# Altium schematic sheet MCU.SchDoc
size A4; SheetNumber: 2; SheetTotal: 2
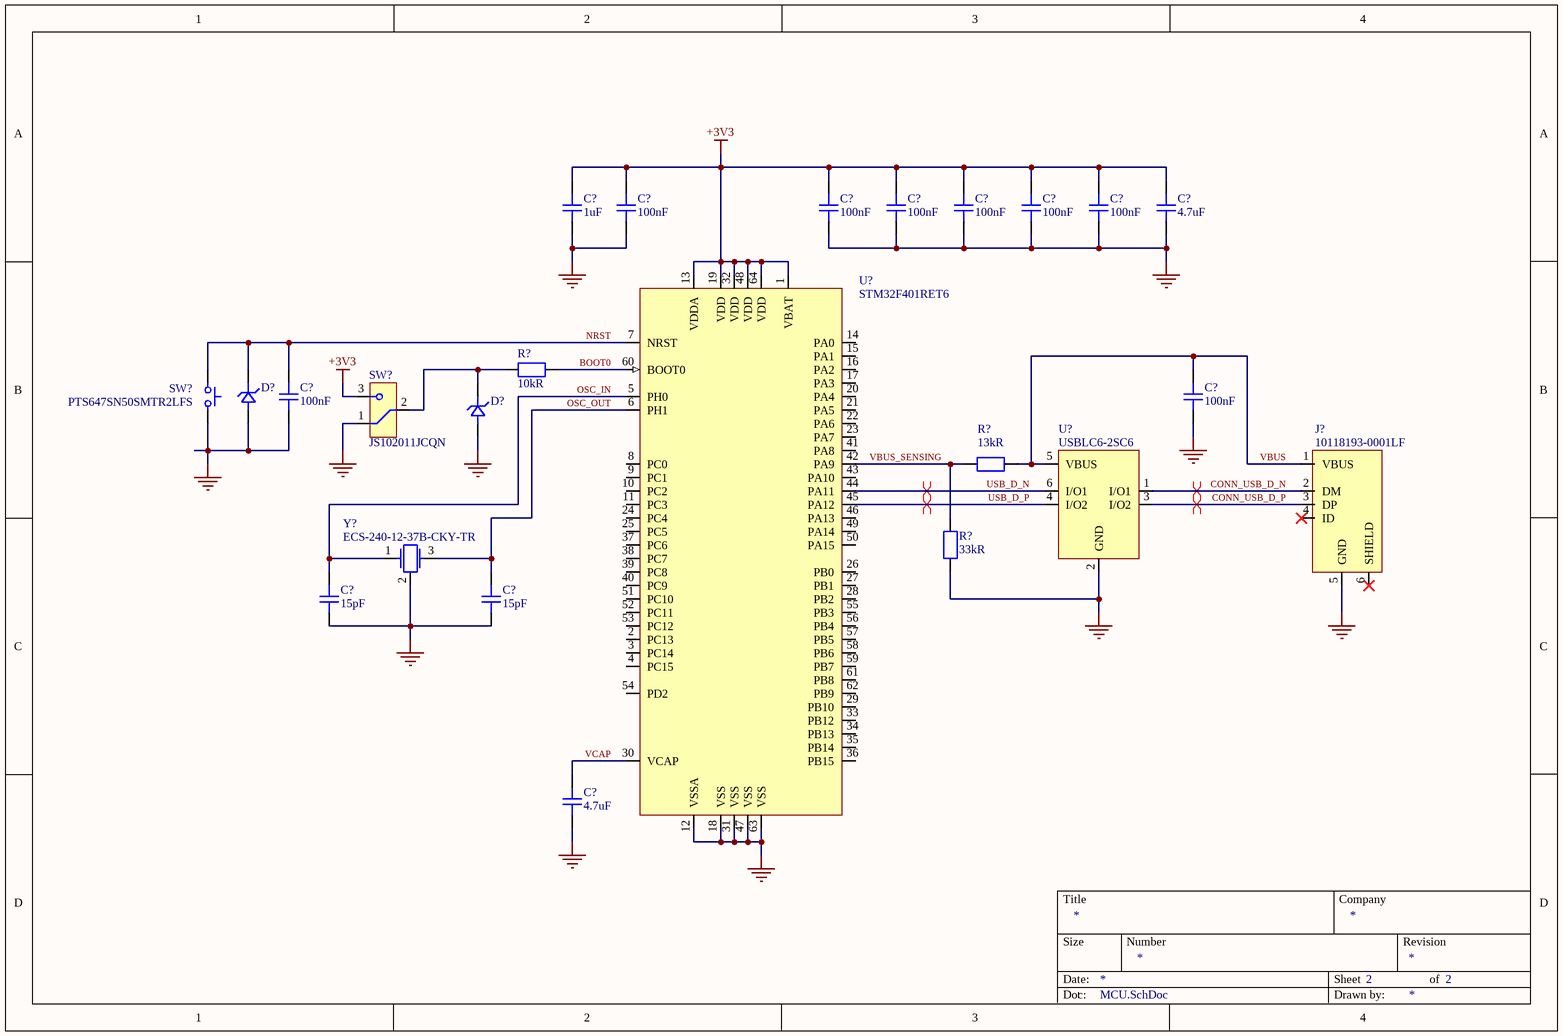
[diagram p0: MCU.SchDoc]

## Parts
(Parts that share a designator on the sheet are numbered #1, #2 ... from top to bottom, then left to right.)
C?#1  value 1uF  [C_Yageo_CC_0402_A]  (hidden comment: CC0402MRX5R6BB105)
C?#2  value 100nF  [C_Yageo_CC_0402_A]  (hidden comment: CC0402MRX5R6BB104)
C?#3  value 100nF  [C_Yageo_CC_0402_A]  (hidden comment: CC0402MRX5R6BB104)
C?#4  value 100nF  [C_Yageo_CC_0402_A]  (hidden comment: CC0402MRX5R6BB104)
C?#5  value 100nF  [C_Yageo_CC_0402_A]  (hidden comment: CC0402MRX5R6BB104)
C?#6  value 100nF  [C_Yageo_CC_0402_A]  (hidden comment: CC0402MRX5R6BB104)
C?#7  value 100nF  [C_Yageo_CC_0402_A]  (hidden comment: CC0402MRX5R6BB104)
C?#8  value 4.7uF  [C_Yageo_CC_0402_A]  (hidden comment: CC0402MRX5R6BB475)
C?#9  value 100nF  [C_Yageo_CC_0402_A]  (hidden comment: CC0402MRX5R6BB104)
C?#10  value 100nF  [C_Yageo_CC_0402_A]  (hidden comment: CC0402MRX5R6BB104)
C?#11  value 15pF  [C_Yageo_CC_0402_A]  (hidden comment: CC0402JRNPO9BN150)
C?#12  value 15pF  [C_Yageo_CC_0402_A]  (hidden comment: CC0402JRNPO9BN150)
C?#13  value 4.7uF  [C_Yageo_CC_0402_A]  (hidden comment: CC0402MRX5R6BB475)
D?#1  CPDU3V3UP  [D_TVS_Uni_CompChipTech_CPDU3V3UP_A]  (value not drawn)
D?#2  CPDU3V3UP  [D_TVS_Uni_CompChipTech_CPDU3V3UP_A]  (value not drawn)
J?  10118193-0001LF  [J_USB_Micro-B_Amphenol_10118193-0001LF]
R?#1  value 10kR  [R_Yageo_RCL_0402_A]  (hidden comment: RC0402FR-0710KL)
R?#2  value 13kR  [R_Yageo_RCL_0402_A]  (hidden comment: RC0402FR-0713KL)
R?#3  value 33kR  [R_Yageo_RCL_0402_A]  (hidden comment: RC0402FR-0733KL)
SW?#1  PTS647SN50SMTR2LFS  [SW_Tactitle_SPST_C&K_PTS647SN50SMTR2LFS]
SW?#2  JS102011JCQN  [SW_Slide_C&K_JS102011JCQN]
U?#1  USBLC6-2SC6  [U_STM32_SOT-23-6L_USBLC6-2-B]
U?#2  STM32F401RET6  [U_STM32F401xD/xE_B]
Y?  ECS-240-12-37B-CKY-TR  [Y_Crystal_GND24_ECS_240-12-37B-CKY-TR]

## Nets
+3V3: C?#1.2 C?#2.2 C?#3.2 C?#4.2 C?#5.2 C?#6.2 C?#7.2 C?#8.2 SW?#2.3 U?#2.1(VBAT) U?#2.13(VDDA) U?#2.19(VDD) U?#2.32(VDD) U?#2.48(VDD) U?#2.64(VDD)
GND: C?#1.1 C?#2.1 C?#3.1 C?#4.1 C?#5.1 C?#6.1 C?#7.1 C?#8.1 C?#9.1 C?#10.1 C?#11.1 C?#12.1 C?#13.1 D?#1.2 D?#2.2 J?.5(GND) R?#3.1 SW?#1.2 SW?#2.1 U?#1.2(GND) U?#2.12(VSSA) U?#2.18(VSS) U?#2.31(VSS) U?#2.47(VSS) U?#2.63(VSS) Y?.2
BOOT0: R?#1.2 U?#2.60(BOOT0)
CONN_USB_D_N: J?.2(DM) U?#1.1(I/O1)
CONN_USB_D_P: J?.3(DP) U?#1.3(I/O2)
NRST: C?#9.2 D?#1.1 SW?#1.1 U?#2.7(NRST)
OSC_IN: C?#11.2 U?#2.5(PH0) Y?.1
OSC_OUT: C?#12.2 U?#2.6(PH1) Y?.3
USB_D_N: U?#1.6(I/O1) U?#2.44(PA11)
USB_D_P: U?#1.4(I/O2) U?#2.45(PA12)
VBUS: C?#10.2 J?.1(VBUS) R?#2.2 U?#1.5(VBUS)
VBUS_SENSING: R?#2.1 R?#3.2 U?#2.42(PA9)
VCAP: C?#13.2 U?#2.30(VCAP)
NetD?#2_1: D?#2.1 R?#1.1 SW?#2.2

Not connected (* = marked no-connect by the designer): J? 4(ID)* 6(SHIELD)*; U?#2 2(PC13) 3(PC14) 4(PC15) 8(PC0) 9(PC1) 10(PC2) 11(PC3) 14(PA0) 15(PA1) 16(PA2) 17(PA3) 20(PA4) 21(PA5) 22(PA6) 23(PA7) 24(PC4) 25(PC5) 26(PB0) 27(PB1) 28(PB2) 29(PB10) 33(PB12) 34(PB13) 35(PB14) 36(PB15) 37(PC6) 38(PC7) 39(PC8) 40(PC9) 41(PA8) 43(PA10) 46(PA13) 49(PA14) 50(PA15) 51(PC10) 52(PC11) 53(PC12) 54(PD2) 55(PB3) 56(PB4) 57(PB5) 58(PB6) 59(PB7) 61(PB8) 62(PB9)

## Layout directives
differential pair; differential pair class USB: CONN_USB_D_N, CONN_USB_D_P
differential pair: USB_D_N, USB_D_P

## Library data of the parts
C?#1 = CMP-001-00016-7: Multilayer Ceramic Capacitor, 1 uF, 50 V, ± 10%, X5R, 0402 [1005 Metric]; Voltage Rating (DC): 10V; Tolerance: 20%; Temperature Coefficient: 30ppm/°C
C?#2-C?#7 C?#9 = CMP-001-00009-8: Multilayer Ceramic Capacitor, 0.1 uF, 25 V, ± 20%, X7R, 0402 [1005 Metric]; Dielectric: X5R; Temperature Coefficient: 30ppm/°C; Voltage Rating: 10V
C?#8 C?#13 = CMP-001-00015-8: Multilayer Ceramic Capacitor, 4.7 uF, 50 V, ± 10%, X5R, 0402 [1005 Metric]; Tolerance: 20%; Temperature Coefficient: 30ppm/°C; Voltage Rating (DC): 10V
C?#10 = CMP-001-00009-8: Multilayer Ceramic Capacitor, 0.1 uF, 25 V, ± 20%, X7R, 0402 [1005 Metric]; Voltage Rating (DC): 10V; Temperature Coefficient: 30ppm/°C; Dielectric: X5R
C?#11 C?#12 = CMP-001-00017-9: Multilayer Ceramic Capacitor, 15 pF, 10 V, ± 5%, X7R, 0402 [1005 Metric]; Insulation Resistance: 100GR; Dielectric: C0G; Voltage Rating (DC): 50V; Temperature Coefficient: 30ppm/°C
D?#1 D?#2 = CMP-004-00001-2: ESD Suppressor Diode TVS Uni-Dir 3.3V 2-Pin SOD-523F T/R; Clamping Voltage: 8V; Power Line Protection: No; Number of Unidirectional Channels: 1; Diode Type: ZENER; Peak Pulse Current: 5A; Peak Pulse Power: 40W
J? = CMP-002-00002-7: Usb Connector, 5 Contact(S), Female, Right Angle, Surface Mount Terminal, Locking, Receptacle; Number of Contacts: 5; Current Rating: 1.8A; Connector Type: USB,Receptacle; Pitch: 650um; Number of Ports: 1; Voltage Rating: 100V; USB Standard: USB 2.0; Insulation Resistance: 1GR
R?#1 = CMP-009-00003-7: SMD Chip Resistor, 10 kOhm, ± 1%, 62.5 mW, 0402 [1005 Metric], Thick Film, General Purpose; Power Rating: 62.5mW; Max Power Dissipation: 63mW; Temperature Coefficient: 100ppm/°C; Voltage Rating (DC): 50V
R?#2 = CMP-009-00001-7: SMD Chip Resistor, 13 kOhm, ± 1%, 63 mW, 0402 [1005 Metric], Thick Film, General Purpose; Voltage Rating (DC): 50V; Temperature Coefficient: 100ppm/°C; Max Power Dissipation: 63mW; Power Rating: 62.5mW
R?#3 = CMP-009-00005-8: SMD Chip Resistor, 33 kOhm, ± 1%, 63 mW, 0402 [1005 Metric], Thick Film, General Purpose; Power Rating: 63mW; Temperature Coefficient: 100ppm/°C; Voltage Rating (AC): 50V
SW?#1 = CMP-011-00000-10: Switch Tactile N.O. SPST Round Button Gull Wing 0.05A 12VDC 100000Cycles 0.98N SMD T/R; pin to pad: 1>1+2 2>3+4; Ratings: IP40; Switch Function: Off-Mom; Illumination Type: Non-Illuminated; Actuator Type: Standard; Number of Positions: 2; Operating Force: 100gf; Switch Travel: 0.25mm
SW?#2 = CMP-011-00001-7: JS Series Sub-Miniature Slide Switch SPDT On-On Top Slide 0.3A 6VDC J-Lead Surface Mount T/R; Voltage Rating (DC): 6V; Switch Travel: 2mm; Actuator Material: Nylon,Polyamide,PA46; Electrical Life: 5000Cycles; Actuator Type: Standard
U?#1 = CMP-015-00000-1: ESD Suppressor Diode Arrays Uni-Dir 15kV@Air Gap/8kV@Contact Disc 6-Pin SOT-23 T/R; Max Breakdown Voltage: 6V; Direction: Unidirectional,Bidirectional; Peak Pulse Current: 5A; Clamping Voltage-Max: 17V; Number of Bidirectional Channels: 2; Value: 3.5pF; Test Current: 1mA; ESD Protection: Yes; Max Reverse Leakage Current: 150nA; Operating Supply Voltage: 1.1V; Reverse Standoff Voltage: 5.25V; Number of Elements: 1; Working Voltage: 5V; Data Rate: 480Mbps
U?#2 = CMP-020-00000-6: MCU 32-bit STM32 ARM Cortex M4 RISC 512KB Flash 1.8V/2.5V/3.3V 64-Pin LQFP Tray; Operating Supply Voltage: 3.3V; Peripherals: Brown-out Detect/Reset,POR,PWM,WDT,DMA; Nominal Supply Current: 1.8uA; Number of ADC Channels: 12; Interface: I2C,SPI,USB,IrDA,SDIO,UART,USART,LIN,I2S; Clock Frequency: 84MHz; Number of USB Channels: 1; Number of Timers/Counters: 8; Number of Channels: 16; Number of PWM Channels: 23; Number of UART Channels: 3; Number of Programmable I/O: 50; Watchdog Timer: Yes; Max Power Dissipation: 313mW; Min Supply Voltage: 1.7V; Data Bus Width: 32b; RAM Size: 96KB; Max Supply Voltage: 3.6V; Oscillator Type: Internal
Y? = CMP-003-00000-4: Crystal 24MHz ±10ppm (Tol) ±10ppm (Stability) 12pF FUND 50Ohm 4-Pin Mini-CSMD T/R; pin to pad: 2>2+4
